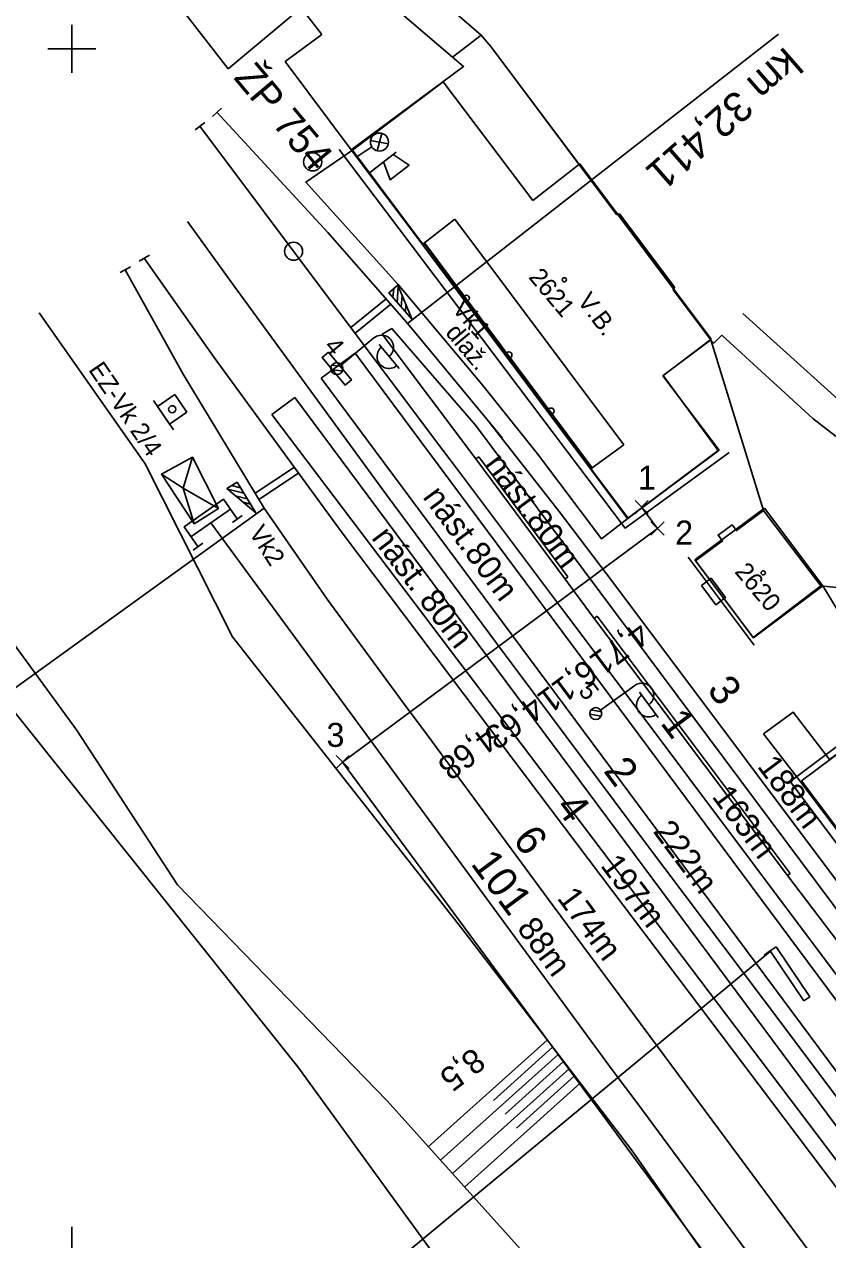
# Model space of a CAD drawing. Extents: x -804166 to -803706, y -1151030 to -1150147.
# Drawn here: x -804103.9 to -804037.2, y -1150299.1 to -1150198 of the extents above; entities that cross this region are included whole.
import ezdxf

# ---------------------------------------------------------------- set-up
doc = ezdxf.new("R2010")
doc.units = 0
for name, color, linetype in [('0381KM032-037P - Vrstva 1', 7, 'Continuous'), ('0381KM032-037P - Vrstva 12', 7, 'Continuous'), ('0381KM032-037P - Vrstva 14', 7, 'Continuous'), ('0381KM032-037P - Vrstva 15', 7, 'Continuous'), ('0381KM032-037P - Vrstva 16', 7, 'Continuous'), ('0381KM032-037P - Vrstva 2', 7, 'Continuous'), ('0381KM032-037P - Vrstva 23', 7, 'Continuous'), ('0381KM032-037P - Vrstva 25', 7, 'Continuous'), ('0381KM032-037P - Vrstva 3', 7, 'Continuous'), ('0381KM032-037P - Vrstva 33', 7, 'Continuous'), ('0381KM032-037P - Vrstva 4', 7, 'Continuous'), ('0381KM032-037P - Vrstva 48', 7, 'Continuous'), ('0381KM032-037P - Vrstva 49', 7, 'Continuous'), ('0381KM032-037P - Vrstva 51', 7, 'Continuous'), ('0381KM032-037P - Vrstva 55', 7, 'Continuous'), ('0381KM032-037P - Vrstva 57', 7, 'Continuous'), ('0381KM032-037P - Vrstva 59', 7, 'Continuous'), ('0381KM032-037P - Vrstva 7', 7, 'Continuous'), ('0381KM032-037P - Vrstva 9', 7, 'Continuous'), ('Default', 7, 'Continuous'), ('hran DP - hran DP', 7, 'Continuous'), ('krizky_1000 - Vrstva 1', 7, 'Continuous'), ('PSR_C2_2_Lomove_body_Vimperk - Vrstva 60', 7, 'Continuous'), ('PSR_C2_2_trasa_Vimperk - Kabelová trasa', 7, 'Continuous'), ('vyt_sit - stávající', 7, 'Continuous')]:
    doc.layers.add(name, color=color, linetype=linetype)

msp = doc.modelspace()

# ---------------------------------------------------------------- linework, layer by layer
at = {"layer": '0381KM032-037P - Vrstva 1'}
for points in [[(-804087.93, -1150205.28), (-804078.71, -1150215.28), (-804072.37, -1150222.52), (-804072.08, -1150222.85), (-804071.47, -1150223.58), (-804065.48, -1150230.82), (-804059.47, -1150238.51), (-804055.55, -1150243.68), (-804054.36, -1150245.27), (-804043.89, -1150259.22), (-804035.37, -1150270.61), (-804034.4, -1150271.93), (-804017.97, -1150293.92), (-804002.6, -1150314.46), (-803985.38, -1150337.43), (-803955.87, -1150376.72)], [(-804089.35, -1150206.44), (-804078.67, -1150220.7), (-804069.15, -1150233.38), (-804067.86, -1150235.11), (-804059.28, -1150246.53), (-804058.07, -1150248.16), (-804048.7, -1150260.65), (-804037.85, -1150275.13), (-804021.63, -1150296.76), (-804006.14, -1150317.34), (-803988.98, -1150340.29), (-803981.9, -1150349.73)], [(-804090.39, -1150214.38), (-804086.65, -1150219.55), (-804073.82, -1150237.11), (-804072.56, -1150238.83), (-804064.05, -1150250.31), (-804062.81, -1150251.97), (-804052.29, -1150266.05), (-804042.5, -1150279.11), (-804026.55, -1150300.33), (-804011.27, -1150320.63), (-803993.37, -1150344.49), (-803965.17, -1150382.07), (-803953.84, -1150397.19)], [(-804093.97, -1150217.42), (-804088.17, -1150225.67), (-804077.51, -1150240.28), (-804068.52, -1150252.21), (-804067.31, -1150253.81), (-804055.01, -1150270.12), (-804046.09, -1150281.93), (-804030.05, -1150303.21), (-804014.76, -1150323.52), (-803996.92, -1150347.35), (-803968.88, -1150385.42), (-803942.6, -1150419.03)], [(-804095.55, -1150218.38), (-804090.74, -1150227.08), (-804084.01, -1150238.21), (-804078.76, -1150245.78), (-804072.11, -1150254.85), (-804070.85, -1150256.55), (-804059.97, -1150271.29), (-804049.56, -1150285.37), (-804034.13, -1150306.22), (-804018.79, -1150326.86), (-804001.18, -1150350.63), (-803980.37, -1150378.68), (-803972.82, -1150388.42), (-803965.21, -1150397.6)], [(-804088.45, -1150239.45), (-804070.36, -1150264.07), (-804054.98, -1150285.05), (-804052.95, -1150287.79), (-804037.56, -1150308.64), (-804021.87, -1150329.91), (-804004.48, -1150353.56), (-803990.76, -1150372.09)]]:
    msp.add_lwpolyline(points, dxfattribs=at)
at = {"layer": '0381KM032-037P - Vrstva 12'}
for p, q in [((-804066.16, -1150233.94), (-804066.4, -1150234.12)), ((-804066.16, -1150233.94), (-804058.75, -1150243.94)), ((-804066.4, -1150234.12), (-804058.99, -1150244.12)), ((-804058.75, -1150243.94), (-804058.99, -1150244.12)), ((-804056.32, -1150247.21), (-804056.56, -1150247.39)), ((-804056.56, -1150247.39), (-804040.5, -1150268.78)), ((-804056.32, -1150247.21), (-804040.26, -1150268.6)), ((-804040.26, -1150268.6), (-804040.5, -1150268.78))]:
    msp.add_line(p, q, dxfattribs=at)
at = {"layer": '0381KM032-037P - Vrstva 14'}
for p, q in [((-804074.2, -1150223.73), (-804073.38, -1150223.27)), ((-804079.27, -1150227.4), (-804076.45, -1150225.31)), ((-804028.77, -1150289.52), (-804076.45, -1150225.31)), ((-804031.59, -1150291.62), (-804079.27, -1150227.4)), ((-804081.46, -1150229.02), (-804083.37, -1150230.42)), ((-804033.77, -1150293.24), (-804081.46, -1150229.02)), ((-804083.37, -1150230.42), (-804035.09, -1150294.23))]:
    msp.add_line(p, q, dxfattribs=at)
for points in [[(-804026.2, -1150287.61), (-804040.5, -1150268.78), (-804056.56, -1150247.39), (-804058.99, -1150244.12), (-804066.4, -1150234.12), (-804074.2, -1150223.73)], [(-804025.08, -1150286.79), (-804066.44, -1150231.31), (-804073.38, -1150223.27)]]:
    msp.add_lwpolyline(points, dxfattribs=at)
at = {"layer": '0381KM032-037P - Vrstva 15'}
for p, q in [((-804090.09, -1150240.6), (-804086.81, -1150238.3)), ((-804086.65, -1150239.41), (-804085.83, -1150238.83)), ((-804089.92, -1150241.7), (-804089.1, -1150241.13))]:
    msp.add_line(p, q, dxfattribs=at)
msp.add_lwpolyline([(-804086.24, -1150239.12), (-804087.39, -1150237.48), (-804090.66, -1150239.78), (-804089.51, -1150241.41)], dxfattribs=at)
at = {"layer": '0381KM032-037P - Vrstva 16'}
msp.add_lwpolyline([(-804076.66, -1150208.44), (-804080.54, -1150211.1), (-804072.9, -1150219.59), (-804065.93, -1150227.88), (-804061.29, -1150233.69), (-804055.95, -1150240.78), (-804053.73, -1150239.04)], dxfattribs=at)
at = {"layer": '0381KM032-037P - Vrstva 2'}
for p, q in [((-804087.56, -1150204.95), (-804088.29, -1150205.62)), ((-804088.95, -1150206.14), (-804089.74, -1150206.75)), ((-804093.53, -1150217.18), (-804094.41, -1150217.66)), ((-804095.11, -1150218.14), (-804095.99, -1150218.62))]:
    msp.add_line(p, q, dxfattribs=at)
at = {"layer": '0381KM032-037P - Vrstva 23'}
for p, q in [((-804069.12, -1150202.75), (-804076.66, -1150208.44)), ((-804061.66, -1150212.61), (-804069.12, -1150202.75)), ((-804076.66, -1150208.44), (-804070.85, -1150216.23)), ((-804057.75, -1150209.57), (-804061.66, -1150212.61)), ((-804046.83, -1150224.17), (-804057.75, -1150209.57)), ((-804054.58, -1150213.81), (-804054.46, -1150213.73)), ((-804049.85, -1150219.86), (-804054.46, -1150213.73)), ((-804070.68, -1150216.13), (-804068.14, -1150214.18)), ((-804054.1, -1150232.95), (-804068.14, -1150214.18)), ((-804056.83, -1150234.94), (-804070.74, -1150216.16)), ((-804056.73, -1150234.87), (-804070.68, -1150216.13)), ((-804049.98, -1150219.96), (-804049.85, -1150219.86)), ((-804050.87, -1150227.2), (-804046.83, -1150224.17)), ((-804046.17, -1150233.38), (-804050.87, -1150227.2)), ((-804056.73, -1150234.87), (-804054.1, -1150232.95)), ((-804046.17, -1150233.38), (-804053.73, -1150239.04)), ((-804056.73, -1150234.87), (-804056.83, -1150234.98)), ((-804053.73, -1150239.04), (-804056.83, -1150234.98)), ((-804042.4, -1150238.22), (-804048.19, -1150242.52)), ((-804037.56, -1150244.69), (-804042.4, -1150238.22)), ((-804048.75, -1150242.29), (-804043.27, -1150249.62))]:
    msp.add_line(p, q, dxfattribs=at)
for points in [[(-804045.33, -1150233.58), (-804054, -1150239.88), (-804077.77, -1150208.37)], [(-804070.85, -1150216.23), (-804070.85, -1150216.23), (-804070.74, -1150216.16), (-804070.68, -1150216.13)], [(-804048.19, -1150242.52), (-804043.32, -1150249.01), (-804037.56, -1150244.69)], [(-804034.08, -1150269.19), (-804040.27, -1150260.96), (-804032.39, -1150255.05)], [(-804039.34, -1150260.91), (-804032.82, -1150256.05), (-804026.77, -1150264.06)], [(-804026.77, -1150264.06), (-804033.29, -1150268.94), (-804039.34, -1150260.91)]]:
    msp.add_lwpolyline(points, dxfattribs=at)
msp.add_lwpolyline([(-804078.65, -1150225.24), (-804079.18, -1150225.67), (-804077.27, -1150227.98), (-804076.75, -1150227.55)], close=True, dxfattribs=at)
for centre in [(-804067.18, -1150220.75), (-804063.65, -1150225.47), (-804060.15, -1150230.14)]:
    msp.add_circle(centre, 0.25, dxfattribs=at)
at = {"layer": '0381KM032-037P - Vrstva 25'}
for p, q in [((-804073.67, -1150207.9), (-804075.16, -1150207.64)), ((-804074.21, -1150207.04), (-804074.61, -1150208.49)), ((-804075.05, -1150208.17), (-804076.31, -1150208.99)), ((-804077.58, -1150226.29), (-804074.89, -1150224.06)), ((-804074.44, -1150224.59), (-804072.78, -1150226.6)), ((-804078.45, -1150226.7), (-804077.5, -1150226.79)), ((-804078.38, -1150226.33), (-804077.51, -1150226.42)), ((-804056.03, -1150255.02), (-804053.2, -1150252.96)), ((-804052.79, -1150253.53), (-804051.26, -1150255.63)), ((-804056.84, -1150255.01), (-804055.97, -1150255.15)), ((-804056.93, -1150255.37), (-804055.99, -1150255.52))]:
    msp.add_line(p, q, dxfattribs=at)
msp.add_lwpolyline([(-804047.64, -1150244.64), (-804046.84, -1150244.05), (-804045.65, -1150245.66), (-804046.45, -1150246.25), (-804047.64, -1150244.64)], dxfattribs=at)
for centre, radius in [((-804074.42, -1150207.76), 0.754), ((-804077.96, -1150226.61), 0.5), ((-804077.96, -1150226.61), 0.5), ((-804056.44, -1150255.31), 0.5), ((-804056.44, -1150255.31), 0.5)]:
    msp.add_circle(centre, radius, dxfattribs=at)
for centre, start, end in [((-804074.25, -1150224.83), 309.662, 129.662), ((-804073.62, -1150225.6), 128.9595, 310.3646), ((-804052.61, -1150253.77), 305.995, 125.995), ((-804052.04, -1150254.59), 125.2924, 306.6976)]:
    msp.add_arc(centre, 1, start, end, dxfattribs=at)
at = {"layer": '0381KM032-037P - Vrstva 3'}
for p, q in [((-804072.08, -1150222.85), (-804041.24, -1150198.77)), ((-804072.95, -1150221.1), (-804072.86, -1150219.76)), ((-804073.64, -1150220.31), (-804073.63, -1150220.3)), ((-804073.3, -1150220.7), (-804073.23, -1150219.95)), ((-804072.61, -1150221.49), (-804072.53, -1150220.52)), ((-804072.26, -1150221.89), (-804072.22, -1150221.27)), ((-804071.91, -1150222.28), (-804071.9, -1150222.04)), ((-804091.42, -1150228.76), (-804092.88, -1150229.76)), ((-804090.42, -1150230.22), (-804091.42, -1150228.76)), ((-804093.21, -1150229.27), (-804091.55, -1150231.71)), ((-804092.88, -1150229.76), (-804091.88, -1150231.22)), ((-804091.88, -1150231.22), (-804090.42, -1150230.22)), ((-804085.69, -1150236.97), (-804087.02, -1150236.65)), ((-804085.97, -1150236.52), (-804086.71, -1150236.34)), ((-804086.24, -1150236.07), (-804086.26, -1150236.06)), ((-804085.42, -1150237.43), (-804086.38, -1150237.19)), ((-804085.14, -1150237.88), (-804085.74, -1150237.73)), ((-804084.01, -1150238.21), (-804117.81, -1150262.63)), ((-804084.87, -1150238.33), (-804085.1, -1150238.28))]:
    msp.add_line(p, q, dxfattribs=at)
for points in [[(-804071.7, -1150222.53), (-804072.9, -1150219.66), (-804073.64, -1150220.31), (-804071.7, -1150222.53)], [(-804084.7, -1150238.62), (-804087.1, -1150236.57), (-804086.25, -1150236.06), (-804084.7, -1150238.62)]]:
    msp.add_lwpolyline(points, dxfattribs=at)
msp.add_circle((-804091.65, -1150229.99), 0.296, dxfattribs=at)
at = {"layer": '0381KM032-037P - Vrstva 33'}
msp.add_line((-804075.25, -1150210.32), (-804073.04, -1150208.6), dxfattribs=at)
msp.add_lwpolyline([(-804073.28, -1150208.79), (-804071.96, -1150209.67), (-804073.54, -1150210.89), (-804074.07, -1150209.4)], dxfattribs=at)
at = {"layer": '0381KM032-037P - Vrstva 4'}
for p, q in [((-804064.23, -1150232.38), (-804065.48, -1150230.82)), ((-804067.86, -1150235.11), (-804069.15, -1150233.38)), ((-804072.56, -1150238.83), (-804073.82, -1150237.11)), ((-804054.36, -1150245.27), (-804055.55, -1150243.68)), ((-804058.07, -1150248.16), (-804059.28, -1150246.53)), ((-804062.81, -1150251.97), (-804064.05, -1150250.31)), ((-804067.31, -1150253.81), (-804068.52, -1150252.21)), ((-804070.85, -1150256.55), (-804072.11, -1150254.85))]:
    msp.add_line(p, q, dxfattribs=at)
at = {"layer": '0381KM032-037P - Vrstva 48'}
for p, q in [((-804060.48, -1150282.47), (-804070.36, -1150291.35)), ((-804060.02, -1150283.07), (-804064.94, -1150287.49)), ((-804059.56, -1150283.67), (-804069.35, -1150292.46)), ((-804059.11, -1150284.26), (-804063.98, -1150288.64)), ((-804058.65, -1150284.86), (-804068.35, -1150293.58)), ((-804058.19, -1150285.46), (-804063.02, -1150289.8)), ((-804057.73, -1150286.05), (-804067.35, -1150294.7))]:
    msp.add_line(p, q, dxfattribs=at)
at = {"layer": '0381KM032-037P - Vrstva 49'}
for q in [(-804089.96, -1150233.98), (-804092.55, -1150235.38), (-804087.81, -1150238.25), (-804089.82, -1150239.52)]:
    msp.add_line((-804090.75, -1150236.55), q, dxfattribs=at)
for points in [[(-804102.72, -1150221.96), (-804093.91, -1150234.53), (-804086.64, -1150248.91), (-804067.58, -1150273.2)], [(-804119.6, -1150227.37), (-804114.18, -1150233.24), (-804110.61, -1150241.24), (-804107.35, -1150246.09), (-804099.61, -1150256.67), (-804091.21, -1150269.57), (-804073.78, -1150287.54), (-804061.47, -1150301.24), (-804053.54, -1150315.4), (-804051.02, -1150318.44), (-804043.41, -1150327.56), (-804036.34, -1150339.31), (-804033.47, -1150348.91), (-804032.83, -1150355.72)], [(-804089.82, -1150239.52), (-804087.81, -1150238.25), (-804089.96, -1150233.98), (-804092.55, -1150235.38), (-804089.82, -1150239.52)], [(-804067.58, -1150273.2), (-804053.47, -1150291.61), (-804044.04, -1150305.1), (-804036.58, -1150319.92), (-804030.41, -1150335.37), (-804026.23, -1150342.57), (-804022.74, -1150350.54)]]:
    msp.add_lwpolyline(points, dxfattribs=at)
at = {"layer": '0381KM032-037P - Vrstva 51'}
for points in [[(-804044.22, -1150222.03), (-804036.31, -1150229.15), (-804029.46, -1150234.23), (-804026.23, -1150236.21)], [(-804027.57, -1150238.43), (-804032.18, -1150235.55), (-804038.4, -1150230.77), (-804045.96, -1150223.83), (-804046.63, -1150224.5), (-804046.89, -1150224.2)], [(-804037.56, -1150244.69), (-804031.31, -1150254.99), (-804027.1, -1150261.05), (-804017.62, -1150257.21), (-804018.95, -1150253.97), (-804019.08, -1150250.33), (-804014.25, -1150251.35)]]:
    msp.add_lwpolyline(points, dxfattribs=at)
at = {"layer": '0381KM032-037P - Vrstva 55'}
for points in [[(-804076.76, -1150208.41), (-804070.92, -1150216.16), (-804056.87, -1150234.96), (-804053.79, -1150239.08), (-804046.26, -1150233.41), (-804050.84, -1150227.18), (-804046.86, -1150224.2), (-804050.01, -1150220.06), (-804049.93, -1150219.91), (-804054.58, -1150213.71), (-804054.7, -1150213.8), (-804057.84, -1150209.6), (-804058.02, -1150209.36), (-804065.16, -1150199.8), (-804065.96, -1150198.88), (-804068.34, -1150200.69), (-804067.42, -1150201.47), (-804069.26, -1150202.82)], [(-804048.13, -1150242.59), (-804045.9, -1150240.94), (-804046.26, -1150240.46), (-804045.09, -1150239.61), (-804044.74, -1150240.08), (-804042.5, -1150238.42), (-804037.73, -1150244.68), (-804043.35, -1150248.97)], [(-804042.49, -1150256.99), (-804040.01, -1150255.2), (-804037.01, -1150259.13), (-804032.83, -1150256.09), (-804033.46, -1150255.26), (-804032.63, -1150254.75), (-804027.25, -1150261.82), (-804028.04, -1150262.42), (-804026.84, -1150264.01), (-804033.36, -1150268.97), (-804039.39, -1150261.01)]]:
    msp.add_lwpolyline(points, close=True, dxfattribs=at)
at = {"layer": '0381KM032-037P - Vrstva 59'}
for centre in [(-804059.05, -1150219.22), (-804042.51, -1150243.6)]:
    msp.add_circle(centre, 0.175, dxfattribs=at)
at = {"layer": '0381KM032-037P - Vrstva 7'}
for p, q in [((-804073.87, -1150220.81), (-804076.8, -1150223.18)), ((-804073.48, -1150221.26), (-804076.44, -1150223.66)), ((-804081.49, -1150234.81), (-804084.75, -1150236.98)), ((-804081.14, -1150235.3), (-804084.44, -1150237.5))]:
    msp.add_line(p, q, dxfattribs=at)
msp.add_circle((-804081.56, -1150216.84), 0.75, dxfattribs=at)
at = {"layer": '0381KM032-037P - Vrstva 9'}
for p, q in [((-804041.91, -1150275.08), (-804093.56, -1150317.87)), ((-804041.93, -1150275.06), (-804042.43, -1150275.4)), ((-804041.43, -1150274.72), (-804041.93, -1150275.06)), ((-804041.93, -1150275.06), (-804039.13, -1150279.2)), ((-804038.63, -1150278.87), (-804041.43, -1150274.72)), ((-804039.13, -1150279.2), (-804038.63, -1150278.87))]:
    msp.add_line(p, q, dxfattribs=at)
at = {"layer": 'hran DP - hran DP'}
for p, q in [((-804068.34, -1150200.69), (-804079.56, -1150191.12)), ((-804094.06, -1150192.49), (-804087, -1150201.67)), ((-804087, -1150201.67), (-804080.94, -1150196.58)), ((-804080.94, -1150196.58), (-804079.2, -1150198.82)), ((-804079.2, -1150198.82), (-804082.27, -1150201.05)), ((-804065.96, -1150198.88), (-804065.16, -1150199.8)), ((-804065.16, -1150199.8), (-804058.84, -1150208.26)), ((-804082.27, -1150201.05), (-804076.76, -1150208.41)), ((-804069.26, -1150202.82), (-804067.42, -1150201.47)), ((-804067.42, -1150201.47), (-804068.34, -1150200.69)), ((-804076.76, -1150208.41), (-804069.26, -1150202.82)), ((-804058.84, -1150208.26), (-804054.7, -1150213.8)), ((-804054.7, -1150213.8), (-804054.58, -1150213.71)), ((-804054.58, -1150213.71), (-804049.93, -1150219.91)), ((-804049.93, -1150219.91), (-804050.01, -1150220.06)), ((-804050.01, -1150220.06), (-804046.86, -1150224.2)), ((-804046.86, -1150224.2), (-804042.5, -1150238.42)), ((-804081.21, -1150284.7), (-804121.35, -1150234.4)), ((-804042.5, -1150238.42), (-804037.73, -1150244.68)), ((-804037.73, -1150244.68), (-804020.87, -1150246.51)), ((-804060.01, -1150313.9), (-804081.21, -1150284.7))]:
    msp.add_line(p, q, dxfattribs=at)
msp.add_lwpolyline([(-804077.91, -1150189.15), (-804072.79, -1150192.97), (-804065.96, -1150198.88)], dxfattribs=at)
at = {"layer": 'krizky_1000 - Vrstva 1'}
for points in [[(-804100, -1150198), (-804100, -1150202)], [(-804102, -1150200), (-804098, -1150200)], [(-804100, -1150298), (-804100, -1150302)]]:
    msp.add_lwpolyline(points, dxfattribs=at)
at = {"layer": 'PSR_C2_2_Lomove_body_Vimperk - Vrstva 60'}
for p, q in [((-804053.17, -1150238.68), (-804052.07, -1150237.58)), ((-804052.07, -1150238.68), (-804053.17, -1150237.58)), ((-804051.85, -1150240.46), (-804050.75, -1150239.36)), ((-804050.75, -1150240.46), (-804051.85, -1150239.36)), ((-804078.03, -1150259.89), (-804076.93, -1150258.79)), ((-804076.93, -1150259.89), (-804078.03, -1150258.79))]:
    msp.add_line(p, q, dxfattribs=at)
at = {"layer": 'PSR_C2_2_trasa_Vimperk - Kabelová trasa'}
msp.add_line((-804077.48, -1150259.34), (-804006.07, -1150356.3), dxfattribs=at)
msp.add_lwpolyline([(-804052.62, -1150238.13), (-804051.3, -1150239.91), (-804077.48, -1150259.34)], dxfattribs=at)
at = {"layer": 'vyt_sit - stávající'}
msp.add_line((-804080.02, -1150209.41), (-804079.92, -1150209.41), dxfattribs=at)
msp.add_circle((-804079.97, -1150209.41), 0.756, dxfattribs=at)

# ---------------------------------------------------------------- texts
at = {"layer": '0381KM032-037P - Vrstva 1'}
for s, height, rotation, p in [('4,71', 2, 216.8648, (-804052.93, -1150247.54)), ('6,11', 2, 216.7727, (-804057.27, -1150250.69)), ('3', 2.5, 306.8758, (-804047.25, -1150253.34)), ('4,63', 2, 217.0219, (-804061.71, -1150253.7)), ('1', 2.5, 306.8648, (-804051.13, -1150256.1)), ('4,68', 2, 216.4419, (-804065.54, -1150256.27)), ('2', 2.5, 306.7727, (-804055.85, -1150260.09)), ('188m', 2, 306.8758, (-804043.07, -1150259.71)), ('163m', 2, 306.8648, (-804046.84, -1150262.22)), ('4', 2.5, 307.0782, (-804059.86, -1150263.12)), ('222m', 2, 306.7727, (-804051.73, -1150265.12)), ('6', 2.5, 306.4846, (-804063.4, -1150265.8)), ('101', 2.5, 306.4445, (-804066.89, -1150267.81)), ('197m', 2, 307.0782, (-804056.11, -1150267.96)), ('174m', 2, 306.4846, (-804059.71, -1150270.67)), ('88m', 2, 306.4445, (-804063.05, -1150273.18))]:
    msp.add_text(s, height=height, rotation=rotation, dxfattribs=at).set_placement(p)
at = {"layer": '0381KM032-037P - Vrstva 14'}
for s, rotation, p in [('nást.80m', 306.522, (-804065.75, -1150234.58)), ('nást.80m', 306.5941, (-804070.88, -1150237.3)), ('nást. 80m', 307.1095, (-804075.14, -1150240.7))]:
    msp.add_text(s, height=2, rotation=rotation, dxfattribs=at).set_placement(p)
at = {"layer": '0381KM032-037P - Vrstva 16'}
msp.add_text('dlaž.', height=1.5, rotation=310.0372, dxfattribs=at).set_placement((-804069, -1150223.65))
at = {"layer": '0381KM032-037P - Vrstva 23'}
msp.add_text('V.B.', height=1.5, rotation=307.1118, dxfattribs=at).set_placement((-804058.03, -1150221))
at = {"layer": '0381KM032-037P - Vrstva 25'}
for s, rotation, p in [('4', 309.662, (-804079.09, -1150224.78)), ('5', 305.995, (-804057.93, -1150253.43))]:
    msp.add_text(s, height=1.5, rotation=rotation, dxfattribs=at).set_placement(p)
at = {"layer": '0381KM032-037P - Vrstva 3'}
for s, height, rotation, p in [('km 32,411', 2.5, 221.1865, (-804040.7, -1150199.75)), ('Vk1', 1.5, 311.1865, (-804068.46, -1150221.68)), ('EZ-Vk 2/4', 1.5, 304.3062, (-804098.66, -1150226.7)), ('Vk2', 1.5, 302.561, (-804085.32, -1150240.25))]:
    msp.add_text(s, height=height, rotation=rotation, dxfattribs=at).set_placement(p)
at = {"layer": '0381KM032-037P - Vrstva 48'}
msp.add_text('8,5', height=2, rotation=217.4721, dxfattribs=at).set_placement((-804066.63, -1150283.02))
at = {"layer": '0381KM032-037P - Vrstva 57'}
for s, rotation, p in [('2621', 310.0368, (-804062.08, -1150219.03)), ('2620', 309.9614, (-804044.95, -1150243.53))]:
    msp.add_text(s, height=1.5, rotation=rotation, dxfattribs=at).set_placement(p)
at = {"layer": 'Default'}
for s, p in [('1', (-804052.92, -1150236.68)), ('2', (-804049.83, -1150241.25)), ('3', (-804078.82, -1150258.08))]:
    msp.add_text(s, height=2, dxfattribs=at).set_placement(p)
at = {"layer": 'vyt_sit - stávající'}
msp.add_text('ŽP 754', height=2.4, rotation=310, dxfattribs=at).set_placement((-804086.61, -1150202.44))

doc.saveas('drawing.dxf')
